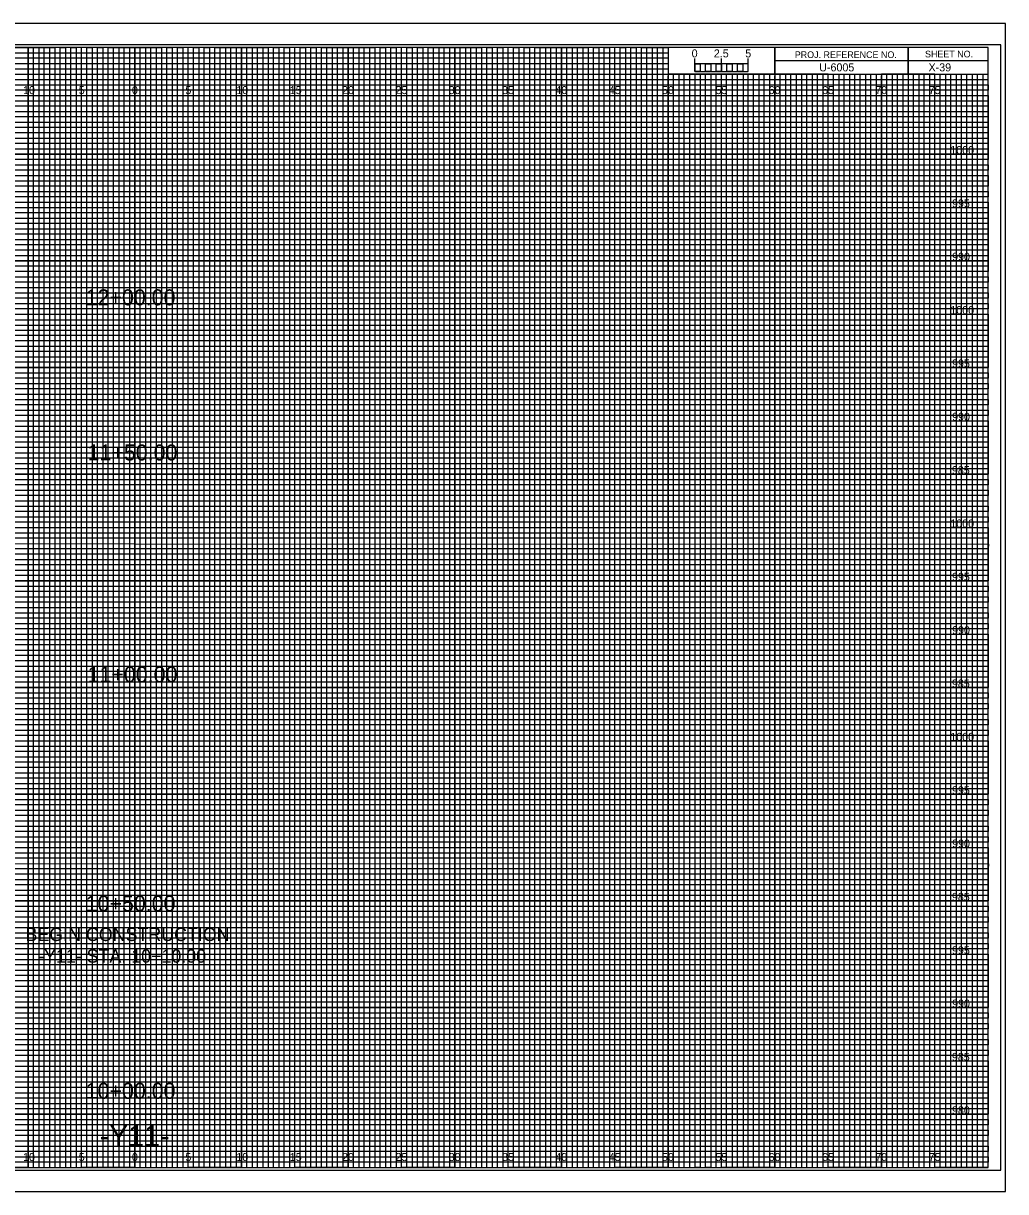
# Model space of a CAD drawing. Extents: x -7 to 162, y -2 to 107.
# Drawn here: x 69.5 to 161.7, y -2.3 to 107.3 of the extents above; entities that cross this region are included whole.
import ezdxf

# ---------------------------------------------------------------- set-up
doc = ezdxf.new("R2010")
doc.units = 0
for name, color, linetype in [('Prop XS Alignment Label', 7, 'Continuous'), ('Prop XS Bar Scale Labels', 7, 'Continuous'), ('Prop XS Elevation Labels', 7, 'Continuous'), ('Prop XS Label Text', 7, 'Continuous'), ('Prop XS Offset Labels', 7, 'Continuous'), ('Prop XS Project Number', 7, 'Continuous'), ('Prop XS Sheet Number', 7, 'Continuous'), ('Prop XS Station Labels', 7, 'Continuous'), ('Sheet Cross Section CELL', 7, 'Continuous'), ('Sheet Cross Section Grid Major CELL', 7, 'Continuous'), ('Sheet Cross Section Grid Middle CELL', 7, 'Continuous'), ('Sheet Cross Section Grid Minor 1 CELL', 7, 'Continuous'), ('Sheet Cross Section Grid Minor 2 CELL', 7, 'Continuous'), ('Sheet Cross Section Scale CELL', 7, 'Continuous'), ('Sheet Cutting Line CELL', 7, 'Continuous'), ('Sheet DOT Grid CELL', 7, 'Continuous'), ('Sheet Plot Border Inside CELL', 7, 'Continuous'), ('Sheet Plot Border Outside CELL', 7, 'Continuous')]:
    doc.layers.add(name, color=color, linetype=linetype)

msp = doc.modelspace()

# ---------------------------------------------------------------- linework, layer by layer
at = {"layer": 'Sheet Cross Section CELL'}
for p, q in [((152.5, 105), (152.5, 102.5)), ((152.5, 102.5), (152.5, 105)), ((160, 103.75), (140, 103.75)), ((140, 103.75), (140, 102.5)), ((140, 102.5), (160, 102.5))]:
    msp.add_line(p, q, dxfattribs=at)
for points in [[(160, 105), (0, 105), (0, 0), (160, 0)], [(140, 105), (130, 105), (130, 102.52), (140, 102.52)], [(160, 105), (140, 105), (140, 102.5), (160, 102.5)]]:
    msp.add_lwpolyline(points, close=True, dxfattribs=at)
at = {"layer": 'Sheet Cross Section Grid Major CELL'}
for p, q in [((75, 105), (70, 105)), ((70, 105), (70, 0)), ((75, 0), (75, 105)), ((85, 105), (80, 105)), ((80, 105), (80, 0)), ((85, 0), (85, 105)), ((95, 105), (90, 105)), ((90, 105), (90, 0)), ((95, 0), (95, 105)), ((105, 105), (100, 105)), ((100, 105), (100, 0)), ((105, 0), (105, 105)), ((115, 105), (110, 105)), ((110, 105), (110, 0)), ((115, 0), (115, 105)), ((125, 105), (120, 105)), ((120, 105), (120, 0)), ((125, 0), (125, 105)), ((130, 105), (130, 0)), ((135, 0), (135, 102.5)), ((145, 102.5), (140, 102.5)), ((140, 102.5), (140, 0)), ((145, 0), (145, 102.5)), ((155, 102.5), (150, 102.5)), ((150, 102.5), (150, 0)), ((155, 0), (155, 102.5)), ((70, 0), (65, 0)), ((80, 0), (75, 0)), ((90, 0), (85, 0)), ((100, 0), (95, 0)), ((110, 0), (105, 0)), ((120, 0), (115, 0)), ((130, 0), (125, 0)), ((140, 0), (135, 0)), ((150, 0), (145, 0)), ((160, 0), (155, 0)), ((160, 0), (160, 0))]:
    msp.add_line(p, q, dxfattribs=at)
for points in [[(0, 100), (160, 100), (160, 95), (0, 95)], [(0, 90), (160, 90), (160, 85), (0, 85)], [(0, 80), (160, 80), (160, 75), (0, 75)], [(0, 70), (160, 70), (160, 65), (0, 65)], [(0, 60), (160, 60), (160, 55), (0, 55)], [(0, 50), (160, 50), (160, 45), (0, 45)], [(0, 40), (160, 40), (160, 35), (0, 35)], [(0, 30), (160, 30), (160, 25), (0, 25)], [(0, 20), (160, 20), (160, 15), (0, 15)], [(0, 10), (160, 10), (160, 5), (0, 5)]]:
    msp.add_lwpolyline(points, dxfattribs=at)
at = {"layer": 'Sheet Cross Section Grid Middle CELL'}
for points in [[(67.5, 105), (72.5, 105), (72.5, 0), (77.5, 0), (77.5, 105), (82.5, 105), (82.5, 0), (87.5, 0), (87.5, 105), (92.5, 105), (92.5, 0), (97.5, 0), (97.5, 105), (102.5, 105), (102.5, 0), (107.5, 0), (107.5, 105), (112.5, 105), (112.5, 0), (117.5, 0), (117.5, 105), (122.5, 105), (122.5, 0), (127.5, 0), (127.5, 105), (129.97, 105), (130, 105), (130, 102.5), (132.5, 102.5), (132.5, 0), (137.5, 0), (137.5, 102.5), (142.5, 102.5), (142.5, 0), (147.5, 0), (147.5, 102.5), (152.5, 102.5), (152.5, 0), (157.5, 0), (157.5, 102.5)], [(0, 102.5), (137.5, 102.5)], [(0, 92.5), (160, 92.5), (160, 97.5), (0, 97.5)], [(0, 82.5), (160, 82.5), (160, 87.5), (0, 87.5)], [(0, 72.5), (160, 72.5), (160, 77.5), (0, 77.5)], [(0, 62.5), (160, 62.5), (160, 67.5), (0, 67.5)], [(0, 52.5), (160, 52.5), (160, 57.5), (0, 57.5)], [(0, 42.5), (160, 42.5), (160, 47.5), (0, 47.5)], [(0, 32.5), (160, 32.5), (160, 37.5), (0, 37.5)], [(0, 22.5), (160, 22.5), (160, 27.5), (0, 27.5)], [(0, 12.5), (160, 12.5), (160, 17.5), (0, 17.5)], [(0, 2.5), (160, 2.5), (160, 7.5), (0, 7.5)]]:
    msp.add_lwpolyline(points, dxfattribs=at)
at = {"layer": 'Sheet Cross Section Grid Minor 1 CELL'}
for p, q in [((0, 104.5), (130, 104.5)), ((130, 104.5), (130, 103.99)), ((130, 103.99), (0, 103.99)), ((0, 103.5), (130, 103.5)), ((130, 102.95), (0, 102.95)), ((130, 103.5), (130, 102.95)), ((0, 102), (160, 102))]:
    msp.add_line(p, q, dxfattribs=at)
for points in [[(0, 101.5), (135, 101.5), (160, 101.5), (160, 101), (0, 101)], [(0, 100.5), (160, 100.5), (160, 99.5), (0, 99.5)], [(0, 99), (160, 99), (160, 98.5), (0, 98.49)], [(0, 98), (160, 98), (160, 97), (0, 97)], [(0, 96.5), (160, 96.5), (160, 96), (0, 96)], [(0, 95.5), (160, 95.5), (160, 94.5), (0, 94.5)], [(0, 94), (160, 94), (160, 93.5), (0, 93.5)], [(0, 93), (160, 93), (160, 92), (0, 92)], [(0, 91.5), (160, 91.5), (160, 91), (0, 91)], [(0, 90.5), (160, 90.5), (160, 89.5), (0, 89.5)], [(0, 89), (160, 89), (160, 88.5), (0, 88.5)], [(0, 88), (160, 88), (160, 86.98), (160, 86.5), (160, 86), (0, 86)], [(0, 87), (160, 87), (160, 86.5), (0, 86.5)], [(0, 85.5), (160, 85.5), (160, 84.5), (0, 84.52)], [(0, 84.52), (160, 84.5), (160, 84), (0, 84)], [(0, 83.5), (160, 83.5), (160, 83), (0, 83)], [(0, 82), (160, 82), (160, 81.5), (0, 81.5)], [(0, 81), (160, 81), (160, 80.5), (0, 80.5)], [(-0.04, 79.45), (160, 79.45), (160, 78.94), (-0.04, 78.94)], [(0, 78.5), (160, 78.5), (160, 78), (0, 78)], [(0, 77), (160, 77), (160, 76.5), (0, 76.5)], [(0, 76), (160, 76), (160, 75.5), (0, 75.5)], [(0, 74.5), (160, 74.5), (160, 74), (0, 74)], [(0, 73.5), (160, 73.5), (160, 73), (0, 73)], [(0, 72), (160, 72), (160, 71.5), (0, 71.5)], [(0, 71), (160, 71), (160, 70.5), (0, 70.5)], [(0, 69.5), (160, 69.5), (160, 68.99), (0, 69)], [(0, 68.5), (160, 68.5), (160, 68), (0, 68)], [(0, 67), (160, 67), (160, 66.5), (0, 66.5)], [(0, 66), (160, 66), (160, 65.5), (0, 65.5)], [(0, 64.5), (160, 64.5), (160, 64), (0, 64)], [(0, 63.5), (160, 63.5), (160, 63), (0, 63)], [(0, 62), (160, 62), (160, 61.5), (0, 61.5)], [(0, 61), (160, 61), (160, 60.5), (0, 60.5)], [(0, 59.5), (160, 59.5), (160, 59), (0, 59)], [(0, 58.5), (160.03, 58.45), (160, 58), (0, 58)], [(0, 57), (160, 57), (160, 56.5), (0, 56.5)], [(0, 56), (160, 56), (160, 55.5), (0, 55.5)], [(0, 54.5), (160, 54.5), (160, 54), (0, 54)], [(0, 53.5), (160, 53.5), (160, 53), (0, 53)], [(0, 52), (160, 52), (160, 51.5), (0, 51.5)], [(0, 51), (160, 51), (160, 50.5), (0, 50.5)], [(0, 49.5), (160, 49.5), (160, 49), (0, 49)], [(0, 48.5), (160, 48.5), (160, 48), (0, 48)], [(0, 47), (160, 47), (160, 46.5), (0, 46.5)], [(0, 46), (160, 46), (160, 45.5), (0, 45.5)], [(0, 44.5), (160, 44.5), (160, 44), (0, 44)], [(0, 43.5), (160, 43.5), (160, 43), (0, 43)], [(0, 42), (160, 42), (160, 41.5), (0, 41.5)], [(0, 41), (160, 41), (160, 40.5), (0, 40.5)], [(0, 39.5), (160, 39.5), (160, 38.99), (0, 39)], [(0, 38.5), (160, 38.5), (160, 38), (0, 38)], [(0, 37), (160, 37), (160, 36.5), (0, 36.5)], [(0, 36), (160, 36), (160, 35.5), (0, 35.5)], [(0, 34.5), (160, 34.5), (160, 34), (0, 34)], [(0, 33.5), (160, 33.5), (160, 33), (0, 33)], [(0, 32), (160, 32), (160, 31.5), (0, 31.5)], [(0, 31), (160, 31), (160, 30.5), (0, 30.5)], [(0, 29.5), (160, 29.5), (160, 29), (0, 29)], [(0, 28.5), (160.03, 28.46), (160, 28), (0, 28)], [(0, 27), (160, 27), (160, 26.5), (0, 26.5)], [(0, 26), (160, 26), (160, 25.5), (0, 25.5)], [(0, 24.5), (160, 24.5), (160, 24), (0, 24)], [(0, 23.5), (160, 23.5), (160, 23), (0, 23)], [(0, 22), (160, 22), (160, 21.5), (0, 21.5)], [(0, 21), (160, 21), (160, 20.5), (0, 20.5)], [(0, 19.5), (160, 19.5), (160, 19), (0, 19)], [(0, 18.5), (160, 18.5), (160, 18), (0, 18)], [(0, 17), (160, 17), (160, 16.5), (0, 16.5)], [(0, 16), (160, 16), (160, 15.5), (0, 15.5)], [(0, 14.5), (160, 14.5), (160, 14), (0, 14)], [(0, 13.5), (160, 13.5), (160, 13), (0, 13)], [(0, 12), (160, 12), (160, 11.5), (0, 11.5)], [(0, 11), (160, 11), (160, 10.5), (0, 10.5)], [(0, 9.5), (160, 9.5), (160, 9), (0, 9)], [(0, 8.5), (160, 8.5), (160, 8), (0, 8)], [(0, 7), (160, 7), (160, 6.5), (0, 6.5)], [(0, 6), (160, 6), (160, 5.5), (0, 5.5)], [(0, 4.5), (160, 4.5), (160, 4), (0, 4)], [(0, 3.5), (160, 3.5), (160, 3), (0, 3)], [(0, 2), (160, 2), (160, 1.5), (0, 1.5)], [(0, 1), (160, 1), (160, 0.5), (0, 0.5)]]:
    msp.add_lwpolyline(points, dxfattribs=at)
at = {"layer": 'Sheet Cross Section Grid Minor 2 CELL'}
for p, q in [((133.5, 102.5), (133, 102.5)), ((133, 102.5), (133, 0)), ((133.5, 0), (133.5, 102.5)), ((134.5, 102.5), (134, 102.5)), ((134, 102.5), (134, 0)), ((134.5, 0), (134.5, 102.5)), ((133, 0), (132.5, 0)), ((134, 0), (133.5, 0))]:
    msp.add_line(p, q, dxfattribs=at)
for points in [[(70, 0), (70.5, 0), (70.5, 105), (71, 105), (71, 0)], [(71, 0), (71.5, 0), (71.5, 105), (72, 105), (72, 0)], [(72.5, 0), (73, 0), (73, 105), (73.5, 105), (73.5, 0)], [(73.5, 0), (74, 0), (74, 105), (74.5, 105), (74.5, 0)], [(75, 0), (75.5, 0), (75.5, 105), (76, 105), (76, 0)], [(76, 0), (76.5, 0), (76.5, 105), (77, 105), (77, 0)], [(77.5, 0), (78, 0), (78, 105), (78.5, 105), (78.5, 0)], [(78.5, 0), (79, 0), (79, 105), (79.5, 105), (79.5, 0)], [(80, 0), (80.5, 0), (80.5, 105), (81, 105), (81, 0)], [(81, 0), (81.5, 0), (81.5, 105), (82, 105), (82, 0)], [(82.5, 0), (83, 0), (83, 105), (83.5, 105), (83.5, 0)], [(83.5, 0), (84, 0), (84, 105), (84.5, 105), (84.5, 0)], [(85, 0), (85.5, 0), (85.5, 105), (86, 105), (86, 0)], [(86, 0), (86.5, 0), (86.5, 105), (87, 105), (87, 0)], [(87.5, 0), (88, 0), (88, 105), (88.5, 105), (88.5, 0)], [(88.5, 0), (89, 0), (89, 105), (89.5, 105), (89.5, 0)], [(90, 0), (90.5, 0), (90.5, 105), (91, 105), (91, 0)], [(91, 0), (91.5, 0), (91.5, 105), (92, 105), (92, 0)], [(92.5, 0), (93, 0), (93, 105), (93.5, 105), (93.5, 0)], [(93.5, 0), (94, 0), (94, 105), (94.5, 105), (94.5, 0)], [(95, 0), (95.5, 0), (95.5, 105), (96, 105), (96, 0)], [(96, 0), (96.5, 0), (96.5, 105), (97, 105), (97, 0)], [(97.5, 0), (98, 0), (98, 105), (98.5, 105), (98.5, 0)], [(98.5, 0), (99, 0), (99, 105), (99.5, 105), (99.5, 0)], [(100, 0), (100.5, 0), (100.5, 105), (101, 105), (101, 0)], [(101, 0), (101.5, 0), (101.5, 105), (102, 105), (102, 0)], [(102.5, 0), (103, 0), (103, 105), (103.5, 105), (103.5, 0)], [(103.5, 0), (104, 0), (104, 105), (104.5, 105), (104.5, 0)], [(105, 0), (105.5, 0), (105.5, 105), (106, 105), (106, 0)], [(106, 0), (106.5, 0), (106.5, 105), (107, 105), (107, 0)], [(107.5, 0), (108, 0), (108, 105), (108.5, 105), (108.5, 0)], [(108.5, 0), (109, 0), (109, 105), (109.5, 105), (109.5, 0)], [(110, 0), (110.5, 0), (110.5, 105), (111, 105), (111, 0)], [(111, 0), (111.5, 0), (111.5, 105), (112, 105), (112, 0)], [(112.5, 0), (113, 0), (113, 105), (113.5, 105), (113.5, 0)], [(113.5, 0), (114, 0), (114, 105), (114.5, 105), (114.5, 0)], [(115, 0), (115.5, 0), (115.5, 105), (116, 105), (116, 0)], [(116, 0), (116.5, 0), (116.5, 105), (117, 105), (117, 0)], [(117.5, 0), (118, 0), (118, 105), (118.5, 105), (118.5, 0)], [(118.5, 0), (119, 0), (119, 105), (119.5, 105), (119.5, 0)], [(120, 0), (120.5, 0), (120.5, 105), (121, 105), (121, 0)], [(121, 0), (121.5, 0), (121.5, 105), (122, 105), (122, 0)], [(122.5, 0), (123, 0), (123, 105), (123.5, 105), (123.5, 0)], [(123.5, 0), (124, 0), (124, 105), (124.5, 105), (124.5, 0)], [(125, 0), (125.5, 0), (125.5, 105), (126, 105), (126, 0)], [(126, 0), (126.5, 0), (126.5, 105), (127, 105), (127, 0)], [(127.5, 0), (128, 0), (128, 105), (128.5, 105), (128.5, 0)], [(128.5, 0), (129, 0), (129, 105), (129.5, 105), (129.5, 0)], [(130, 0), (130.5, 0), (130.5, 102.5), (131.01, 102.5), (131.01, 0)], [(131, 0), (131.5, 0), (131.5, 102.5), (132, 102.5), (132, 0)], [(135, 0), (135.49, 0), (135.49, 102.5), (136, 102.5), (136, 0)], [(136, 0), (136.5, 0), (136.5, 102.5), (137.03, 102.5), (137.03, 0)], [(137.5, 0), (138, 0), (138, 102.5), (138.5, 102.5), (138.5, 0)], [(138.5, 0), (139, 0), (139, 102.5), (139.5, 102.5), (139.5, 0)], [(140, 0), (140.5, 0), (140.5, 102.5), (141, 102.5), (141, 0)], [(141, 0), (141.5, 0), (141.5, 102.5), (142, 102.5), (142, 0)], [(142.5, 0), (143, 0), (143, 102.5), (143.5, 102.5), (143.5, 0)], [(143.5, 0), (144, 0), (144, 102.5), (144.5, 102.5), (144.5, 0)], [(145, 0), (145.5, 0), (145.5, 102.5), (146, 102.5), (146, 0)], [(146, 0), (146.5, 0), (146.5, 102.5), (147, 102.5), (147, 0)], [(147.5, 0), (148, 0), (148, 102.5), (148.5, 102.5), (148.5, 0)], [(148.5, 0), (149, 0), (149, 102.5), (149.5, 102.5), (149.5, 0)], [(150, 0), (150.5, 0), (150.5, 102.5), (151, 102.5), (151, 0)], [(151, 0), (151.5, 0), (151.5, 102.5), (152, 102.5), (152, 0)], [(152.5, 0), (153, 0), (153, 102.5), (153.5, 102.5), (153.5, 0)], [(153.5, 0), (154, 0), (154, 102.5), (154.5, 102.5), (154.5, 0)], [(155, 0), (155.5, 0), (155.5, 102.5), (156, 102.5), (156, 0)], [(156, 0), (156.5, 0), (156.5, 102.5), (157, 102.5), (157, 0)], [(157.5, 0), (158, 0), (158, 102.5), (158.5, 102.5), (158.5, 0)], [(158.5, 0), (159, 0), (159, 102.5), (159.5, 102.5), (159.5, 0)]]:
    msp.add_lwpolyline(points, dxfattribs=at)
at = {"layer": 'Sheet Cross Section Scale CELL'}
for p, q in [((132.5, 102.75), (132.5, 103.95)), ((132.5, 103.45), (132.5, 103.95)), ((135, 102.75), (135, 103.95)), ((137.5, 102.75), (137.5, 103.95)), ((137.5, 103.45), (137.5, 103.95))]:
    msp.add_line(p, q, dxfattribs=at)
for points in [[(137.5, 103.45), (132.5, 103.45), (132.5, 102.75), (137.5, 102.75)], [(132.5, 103.45), (133, 103.45), (133, 102.75), (132.5, 102.75)], [(133.5, 103.45), (134, 103.45), (134, 102.75), (133.5, 102.75)], [(134.5, 103.45), (135, 103.45), (135, 102.75), (134.5, 102.75)], [(135.5, 103.45), (136, 103.45), (136, 102.75), (135.5, 102.75)], [(136.5, 103.45), (137, 103.45), (137, 102.75), (136.5, 102.75)]]:
    msp.add_lwpolyline(points, close=True, dxfattribs=at)
at = {"layer": 'Sheet Cutting Line CELL'}
for p, q in [((161.65, 107.25), (-6.7, 107.25)), ((-6.7, -2.25), (161.65, -2.25))]:
    msp.add_line(p, q, dxfattribs=at)
at = {"layer": 'Sheet DOT Grid CELL'}
for p, q in [((70, 0), (70, 105)), ((75, 0), (75, 105)), ((80, 0), (80, 105)), ((85, 0), (85, 105)), ((90, 0), (90, 105)), ((95, 0), (95, 105)), ((100, 0), (100, 105)), ((105, 0), (105, 105)), ((110, 0), (110, 105)), ((115, 0), (115, 105)), ((120, 0), (120, 105)), ((125, 0), (125, 105)), ((130, 0), (130, 102.34)), ((135, 0), (135, 102.34)), ((140, 0), (140, 102.34)), ((145, 0), (145, 102.34)), ((150, 0), (150, 102.34)), ((155, 0), (155, 102.34)), ((0, 100), (160, 100)), ((0, 95), (160, 95)), ((0, 90), (160, 90)), ((0, 85), (160, 85)), ((0, 80), (160, 80)), ((0, 75), (160, 75)), ((0, 70), (160, 70)), ((0, 65), (160, 65)), ((0, 60), (160, 60)), ((0, 55), (160, 55)), ((0, 50), (160, 50)), ((0, 45), (160, 45)), ((0, 40), (160, 40)), ((0, 35), (160, 35)), ((0, 30), (160, 30)), ((0, 25), (160, 25)), ((0, 20), (160, 20)), ((0, 15), (160, 15)), ((0, 10), (160, 10)), ((0, 5), (160, 5))]:
    msp.add_line(p, q, dxfattribs=at)
at = {"layer": 'Sheet Plot Border Inside CELL'}
msp.add_lwpolyline([(-5.4, -0.25), (161.2, -0.25), (161.2, 105.25), (-5.4, 105.25)], close=True, dxfattribs=at)
at = {"layer": 'Sheet Plot Border Outside CELL'}
msp.add_lwpolyline([(-6.7, -2.25), (161.65, -2.25), (161.65, 107.25), (-6.7, 107.25)], close=True, dxfattribs=at)

# ---------------------------------------------------------------- texts
at = {"layer": 'Prop XS Alignment Label'}
msp.add_text('-Y11-', height=2, dxfattribs=at).set_placement((76.71, 2))
at = {"layer": 'Prop XS Bar Scale Labels'}
for s, p in [('2.5', (134.29, 104.06)), ('5', (137.24, 104.06))]:
    msp.add_text(s, height=0.75, dxfattribs=at).set_placement(p)
at = {"layer": 'Prop XS Elevation Labels'}
for s, p in [('1000', (156.46, 95)), ('995', (156.62, 90)), ('990', (156.63, 85)), ('1000', (156.46, 80)), ('995', (156.62, 75)), ('990', (156.63, 70)), ('985', (156.61, 65)), ('1000', (156.46, 60)), ('995', (156.62, 55)), ('990', (156.63, 50)), ('985', (156.61, 45)), ('1000', (156.46, 40)), ('995', (156.62, 35)), ('990', (156.63, 30)), ('985', (156.61, 25)), ('995', (156.62, 20)), ('990', (156.63, 15)), ('985', (156.61, 10)), ('980', (156.62, 5))]:
    msp.add_text(s, height=0.75, dxfattribs=at).set_placement(p)
at = {"layer": 'Prop XS Label Text'}
for s, p in [('BEGIN CONSTRUCTION', (69.75, 21.24)), ('-Y11- STA. 10+10.00', (70.93, 19.21))]:
    msp.add_text(s, height=1.25, dxfattribs=at).set_placement(p)
at = {"layer": 'Prop XS Offset Labels'}
for s, p in [('10', (69.52, 100.62)), ('5', (74.74, 100.62)), ('0', (79.73, 100.62)), ('0', (79.73, 100.62)), ('5', (84.74, 100.62)), ('10', (89.52, 100.62)), ('15', (94.53, 100.62)), ('20', (99.43, 100.62)), ('25', (104.44, 100.62)), ('30', (109.43, 100.62)), ('35', (114.44, 100.62)), ('40', (119.43, 100.62)), ('45', (124.44, 100.62)), ('50', (129.43, 100.62)), ('55', (134.44, 100.62)), ('60', (139.43, 100.62)), ('65', (144.44, 100.62)), ('70', (149.43, 100.62)), ('75', (154.44, 100.62)), ('10', (69.52, 0.62)), ('5', (74.74, 0.62)), ('0', (79.73, 0.62)), ('0', (79.73, 0.62)), ('5', (84.74, 0.62)), ('10', (89.52, 0.62)), ('15', (94.53, 0.62)), ('20', (99.43, 0.62)), ('25', (104.44, 0.62)), ('30', (109.43, 0.62)), ('35', (114.44, 0.62)), ('40', (119.43, 0.62)), ('45', (124.44, 0.62)), ('50', (129.43, 0.62)), ('55', (134.44, 0.62)), ('60', (139.43, 0.62)), ('65', (144.44, 0.62)), ('70', (149.43, 0.62)), ('75', (154.44, 0.62))]:
    msp.add_text(s, height=0.75, dxfattribs=at).set_placement(p)
at = {"layer": 'Prop XS Project Number'}
msp.add_text('U-6005', height=0.75, dxfattribs=at).set_placement((144.17, 102.75))
at = {"layer": 'Prop XS Sheet Number'}
msp.add_text('X-39', height=0.75, dxfattribs=at).set_placement((154.42, 102.75))
at = {"layer": 'Prop XS Station Labels'}
for s, p in [('12+00.00', (75.39, 80.82)), ('11+50.00', (75.57, 66.28)), ('11+00.00', (75.57, 45.48)), ('10+50.00', (75.39, 24.01)), ('10+00.00', (75.39, 6.45))]:
    msp.add_text(s, height=1.5, dxfattribs=at).set_placement(p)
at = {"layer": 'Sheet Cross Section CELL'}
for s, p in [('PROJ. REFERENCE NO.', (141.88, 104)), ('SHEET NO.', (154.09, 104.06))]:
    msp.add_text(s, height=0.625, dxfattribs=at).set_placement(p)
at = {"layer": 'Sheet Cross Section Scale CELL'}
msp.add_text('0', height=0.75, dxfattribs=at).set_placement((132.21, 104.06))

doc.saveas('drawing.dxf')
